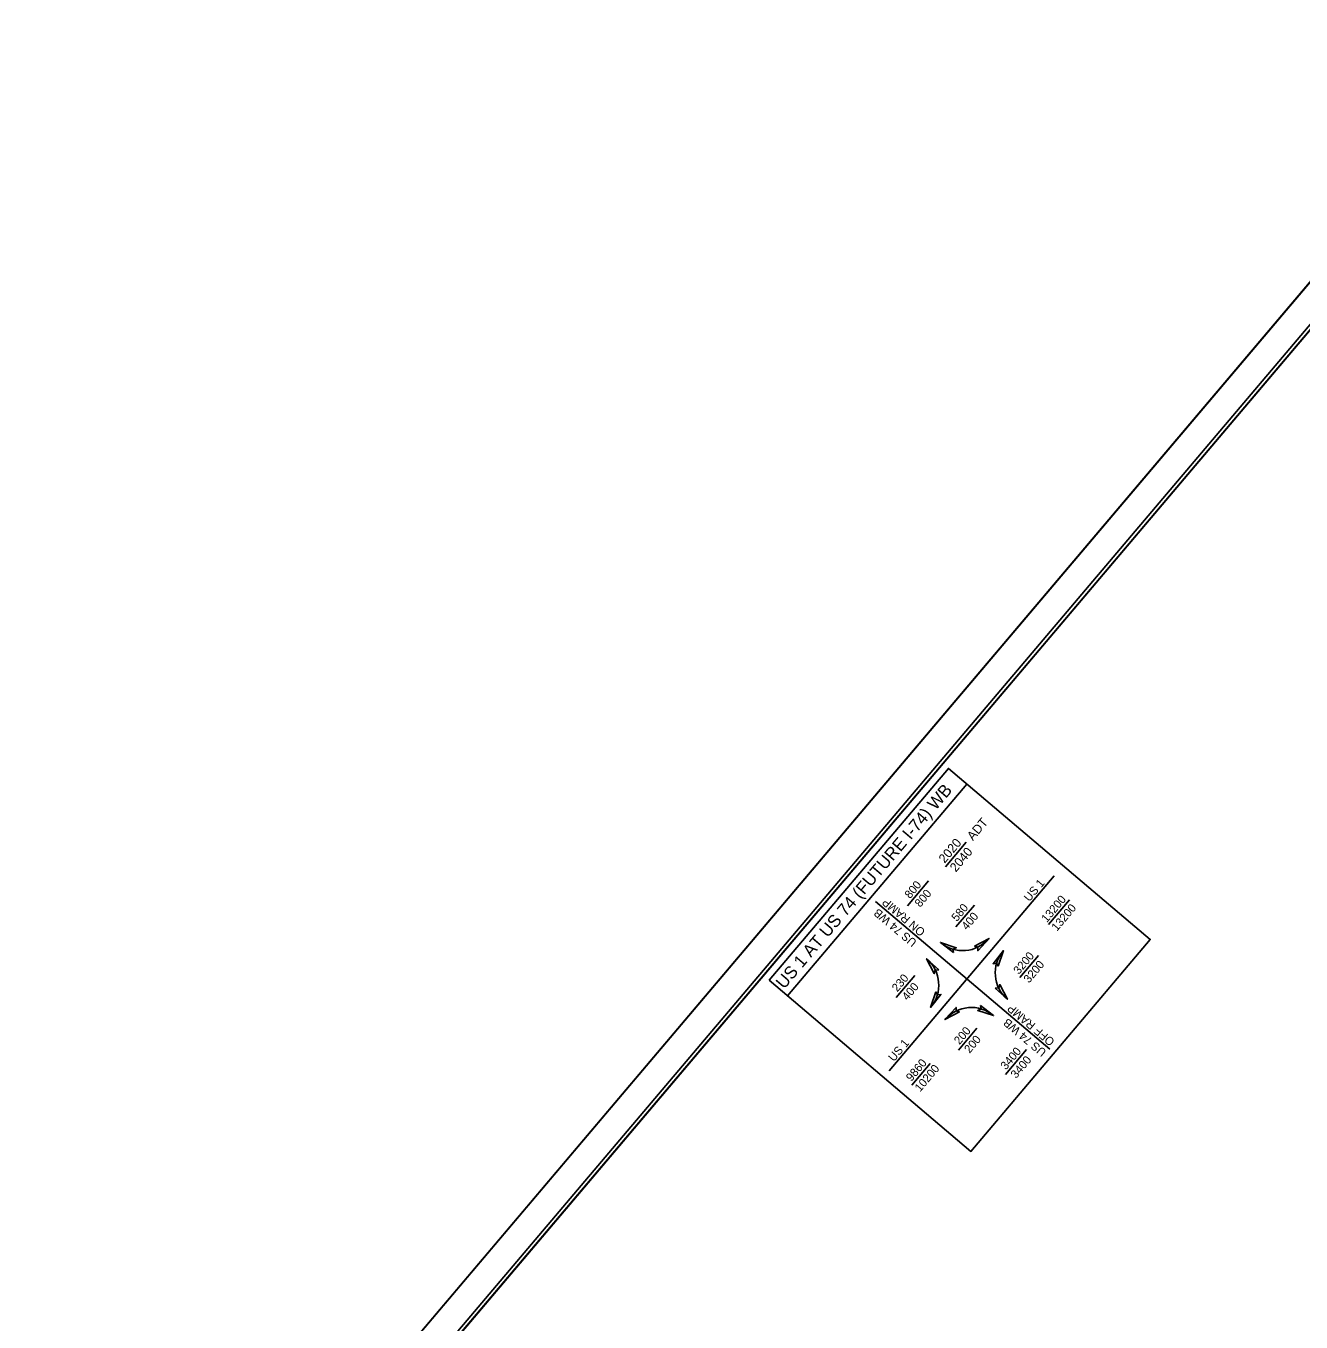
# Model space of a CAD drawing. Extents: x 1761124 to 1763803, y 421930 to 424918.
# Drawn here: x 1761880 to 1762804, y 423880 to 424820 of the extents above; entities that cross this region are included whole.
import ezdxf

# ---------------------------------------------------------------- set-up
doc = ezdxf.new("R2010")
doc.units = 0
for name, color, linetype in [('CTL Sheet Datum Description CELL', 7, 'Continuous'), ('Exist Other Culture Fence Line', 7, 'Continuous'), ('Exist Roads Change in Surface', 7, 'Continuous'), ('Exist Roads Change in Surface Text', 7, 'Continuous'), ('Exist Roads EOP Other', 7, 'Continuous'), ('Exist Roads Soil', 7, 'Continuous'), ('Exist Roads Soil Text', 7, 'Continuous'), ('Exist Structure Major Deck Tunnel Box Culvert', 7, 'Continuous'), ('Exist Structure Major Deck Tunnel Box Culvert Text', 7, 'Continuous')]:
    doc.layers.add(name, color=color, linetype=linetype)

msp = doc.modelspace()

# ---------------------------------------------------------------- linework, layer by layer
at = {"layer": 'CTL Sheet Datum Description CELL'}
msp.add_lwpolyline([(1762004.42, 423647.67), (1762290.12, 423405.67), (1762365.05, 423494.02), (1762431.11, 423438.06), (1762620.91, 423277.27), (1762680.29, 423186), (1762663.1, 423167.95), (1762828.75, 422996.34), (1763720.34, 424048.79), (1763103.2, 424571.6), (1763016.39, 424468.96), (1762832.28, 424624.92), (1762079.3, 423736.09)], close=True, dxfattribs=at)
at = {"layer": 'Exist Roads Change in Surface'}
msp.add_lwpolyline([(1762715.14, 422827.41), (1763803.34, 424111.93), (1762967.84, 424819.73), (1761879.65, 423535.21)], close=True, dxfattribs=at)
at = {"layer": 'Exist Roads Change in Surface Text'}
msp.add_line((1762967.84, 424819.73), (1761879.65, 423535.21), dxfattribs=at)
at = {"layer": 'Exist Roads EOP Other'}
for points in [[(1762974.03, 424792.24), (1762004.42, 423647.7), (1762805.58, 422968.99), (1763775.17, 424113.51)], [(1762805.58, 422968.99), (1762004.42, 423647.67), (1762844.69, 424639.59), (1762959.2, 424542.6), (1763088.51, 424695.22), (1763775.17, 424113.51)]]:
    msp.add_lwpolyline(points, close=True, dxfattribs=at)
at = {"layer": 'Exist Roads Soil'}
msp.add_lwpolyline([(1762708.28, 422850.26), (1763785.15, 424121.43), (1762980.19, 424803.37), (1761903.31, 423532.2)], close=True, dxfattribs=at)
at = {"layer": 'Exist Roads Soil Text'}
for points in [[(1762552.09, 424148.18), (1762542.65, 424155.57), (1762554.1, 424151.78), (1762551.78, 424150.65)], [(1762567.31, 424152.85), (1762577.89, 424158.48), (1762569.79, 424149.55), (1762569.7, 424152.13)], [(1762541.45, 424135.62), (1762532.61, 424143.71), (1762538.22, 424133.04), (1762538.96, 424135.52)], [(1762584.53, 424138.27), (1762588.34, 424149.63), (1762580.86, 424140.17), (1762583.42, 424140.5)], [(1762582.41, 424122.48), (1762591.26, 424114.39), (1762585.64, 424125.07), (1762584.91, 424122.59)], [(1762539.34, 424119.84), (1762535.52, 424108.47), (1762543.01, 424117.93), (1762540.44, 424117.6)], [(1762556.56, 424105.25), (1762545.98, 424099.62), (1762554.08, 424108.55), (1762554.17, 424105.97)], [(1762571.78, 424109.93), (1762581.21, 424102.54), (1762569.76, 424106.32), (1762572.09, 424107.45)]]:
    msp.add_lwpolyline(points, close=True, dxfattribs=at)
at = {"layer": 'Exist Structure Major Deck Tunnel Box Culvert'}
msp.add_lwpolyline([(1762004.42, 423647.67), (1762805.58, 422968.99), (1763775.16, 424113.5), (1763135.37, 424655.51), (1762980.72, 424472.96), (1762819.36, 424609.66)], close=True, dxfattribs=at)
at = {"layer": 'Exist Structure Major Deck Tunnel Box Culvert Text'}
for p, q in [((1762431.73, 424116.87), (1762561.78, 424270.38)), ((1762546.32, 424210.28), (1762561.45, 424228.15)), ((1762505.61, 424062.57), (1762625.23, 424203.77)), ((1762518.82, 424182.11), (1762534.11, 424200.15)), ((1762495.53, 424185.28), (1762561.96, 424129.05)), ((1762553.83, 424166.78), (1762567.27, 424182.65)), ((1762621.13, 424168.5), (1762636.25, 424186.35)), ((1762600.31, 424130.23), (1762613.75, 424146.09)), ((1762510.63, 424115.78), (1762524.07, 424131.64)), ((1762622.06, 424078.12), (1762561.94, 424129.06)), ((1762555.71, 424077.58), (1762569.15, 424093.45)), ((1762589.9, 424059.88), (1762605.19, 424077.92)), ((1762521.94, 424052.13), (1762535.15, 424067.73))]:
    msp.add_line(p, q, dxfattribs=at)
msp.add_lwpolyline([(1762418.41, 424128.16), (1762548.46, 424281.67), (1762694.78, 424157.71), (1762564.73, 424004.2)], close=True, dxfattribs=at)
for centre, start, end in [((1762558.81, 424174.64), 229.7301, 319.7301), ((1762516.45, 424124.63), 319.7301, 49.7301), ((1762607.42, 424133.47), 139.7301, 229.7301), ((1762565.05, 424083.46), 49.7301, 139.7301)]:
    msp.add_arc(centre, 25, start, end, dxfattribs=at)

# ---------------------------------------------------------------- texts
at = {"layer": 'Exist Other Culture Fence Line'}
for s, height, rotation, p in [('US 1 AT US 74 (FUTURE I-74) WB', 9, 49.70132, (1762429.35, 424121.3)), ('ADT', 6.561, 49.70132, (1762566.28, 424228.92)), ('2020', 6.561, 49.70132, (1762545.76, 424212.56)), ('2040', 6.561, 49.70132, (1762553.88, 424206.13)), ('800', 6, 49.70132, (1762520.62, 424186.86)), ('US 1', 6, 49.70132, (1762607.12, 424184.7)), ('800', 6, 49.70132, (1762527.98, 424180.62)), ('13200', 6, 49.70132, (1762619.79, 424169.54)), ('US 74 WB', 6, 139.78282, (1762526.06, 424156.42)), ('ON RAMP', 6, 139.78282, (1762532.16, 424164.03)), ('580', 6, 49.70132, (1762554.6, 424170.31)), ('13200', 6, 49.70132, (1762627.15, 424163.3)), ('400', 6, 49.70132, (1762561.96, 424164.07)), ('3200', 6, 49.70132, (1762599.53, 424131.95)), ('3200', 6, 49.70132, (1762606.9, 424125.7)), ('230', 6, 49.70132, (1762511.39, 424119.31)), ('400', 6, 49.70132, (1762518.75, 424113.06)), ('OFF RAMP', 6, 139.78282, (1762626.02, 424084.52)), ('200', 6, 49.70132, (1762556.47, 424081.11)), ('US 74 WB', 6, 139.78282, (1762620, 424076.83)), ('US 1', 6, 49.70132, (1762508.9, 424068.76)), ('200', 6, 49.70132, (1762563.84, 424074.87)), ('3400', 6, 49.70132, (1762590.17, 424062.82)), ('9860', 6, 49.70132, (1762521.66, 424054.43)), ('10200', 6, 49.70132, (1762527.96, 424046.93)), ('3400', 6, 49.70132, (1762597.53, 424056.58))]:
    msp.add_text(s, height=height, rotation=rotation, dxfattribs=at).set_placement(p)

doc.saveas('drawing.dxf')
